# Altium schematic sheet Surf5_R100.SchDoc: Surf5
size A3; DrawnBy: Jaden; Revision: 1.0; SheetNumber: 1; SheetTotal: 1
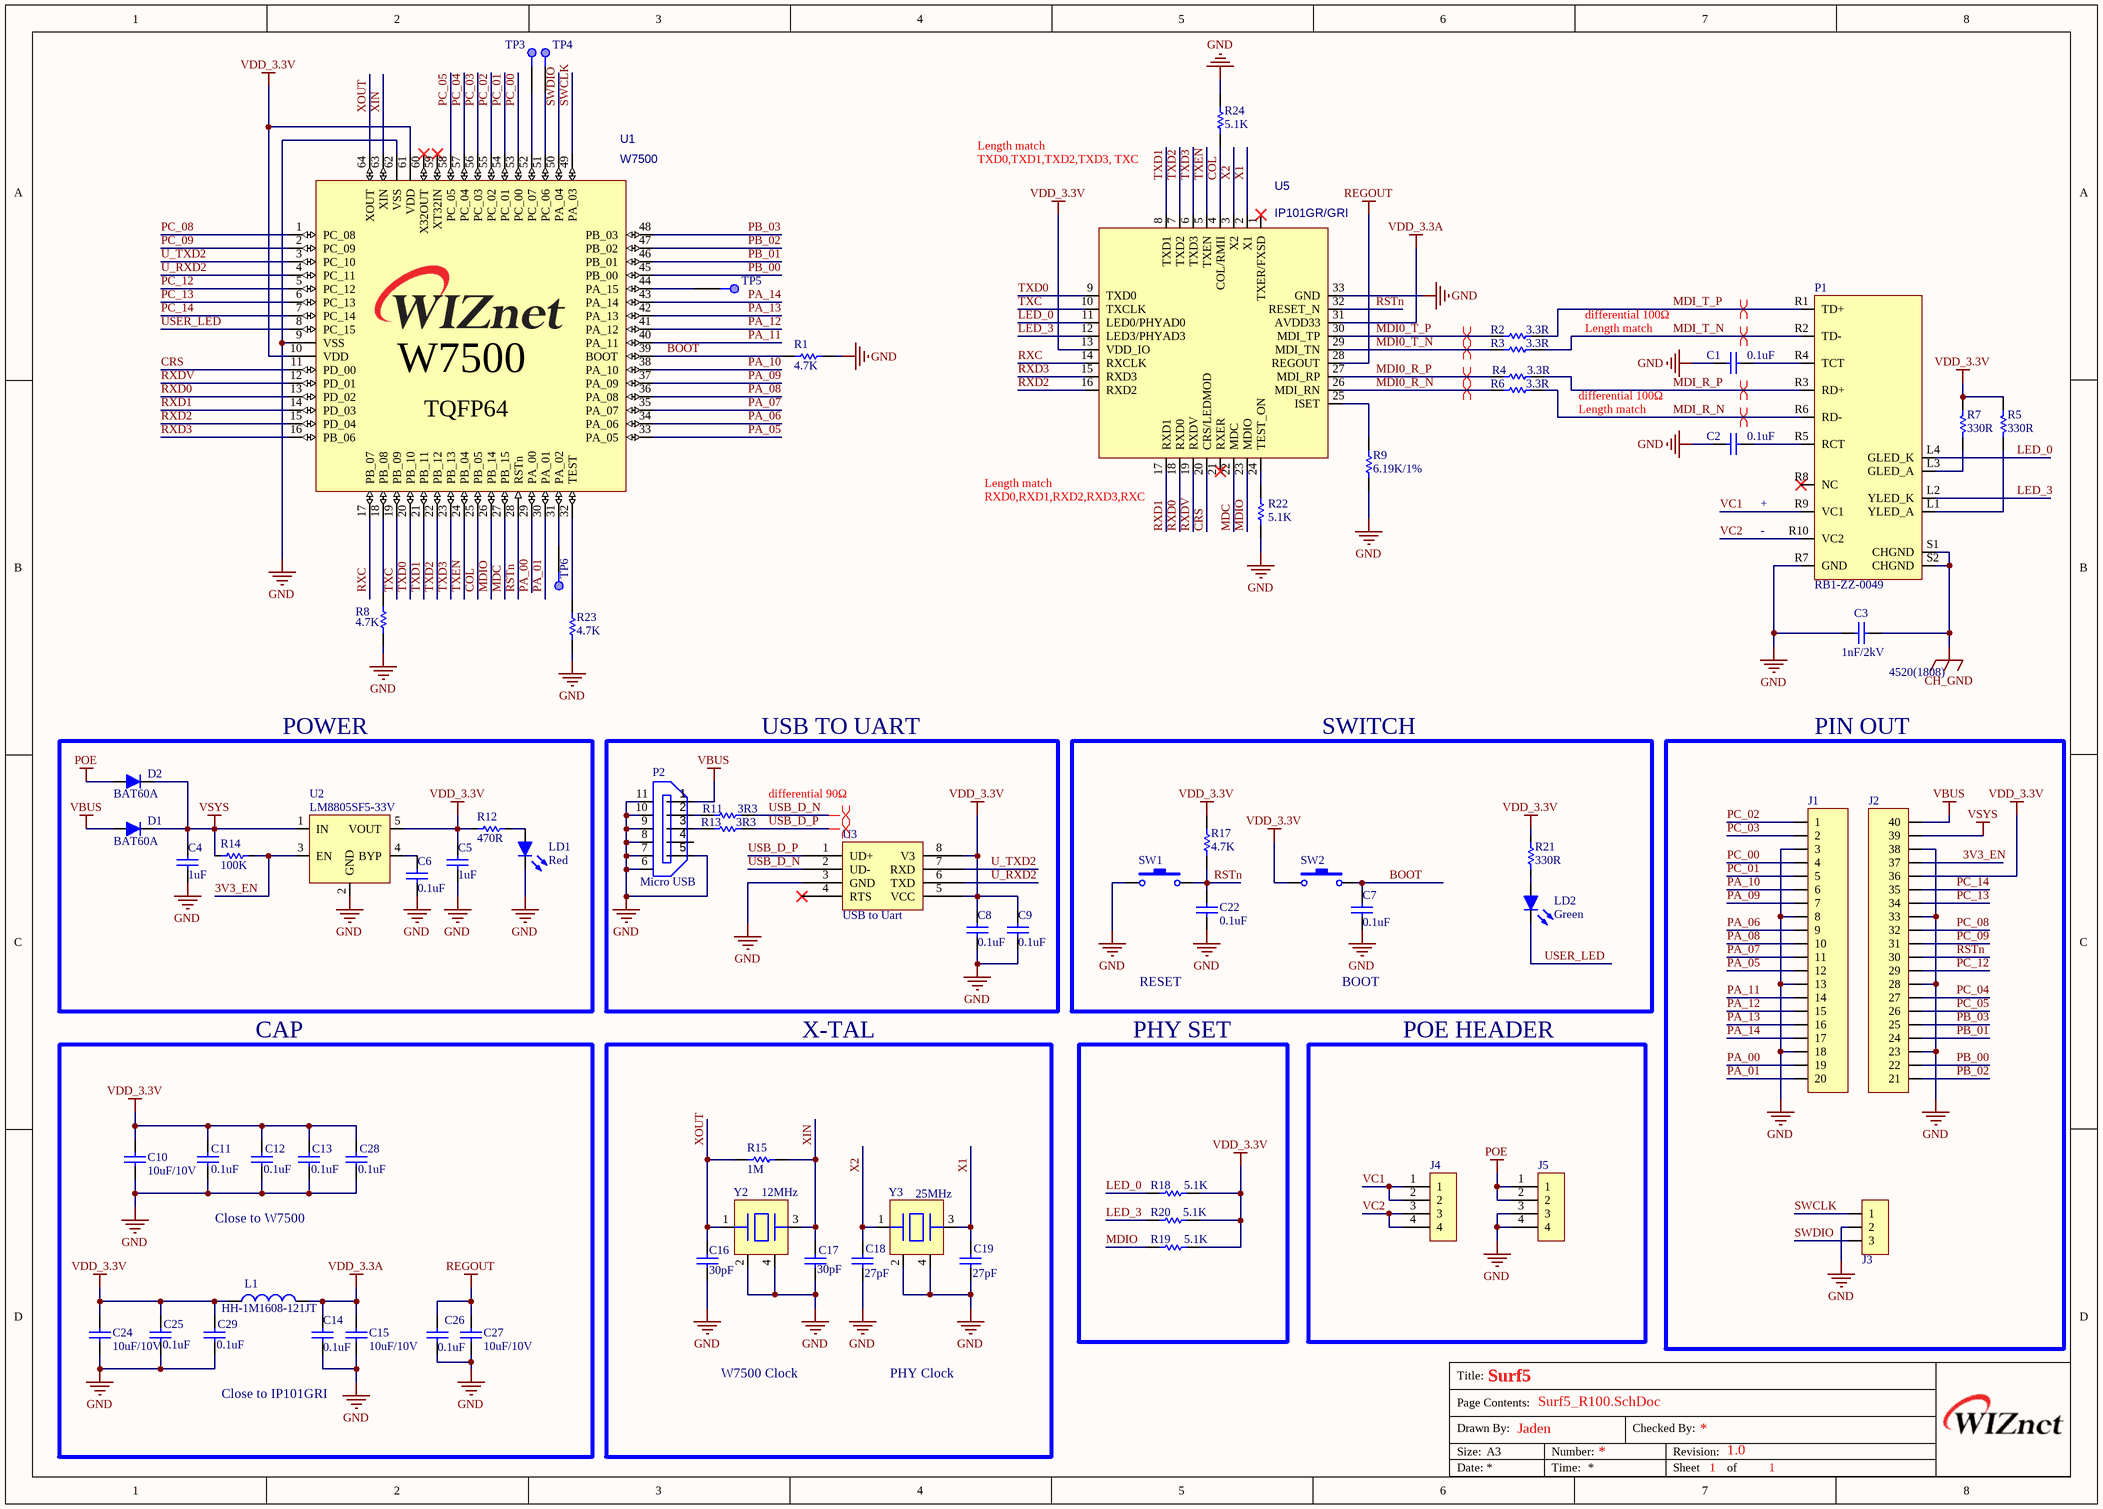
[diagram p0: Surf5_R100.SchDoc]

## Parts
C1  0.1uF  [CAP-0402]
C2  0.1uF  [CAP-0402]
C3  1nF/2kV  [CAP-1808]
C4  1uF  [CAP-0402]
C5  1uF  [CAP-0402]
C6  0.1uF  [CAP-0402]
C7  0.1uF  [CAP-0402]
C8  0.1uF  [CAP-0402]
C9  0.1uF  [CAP-0402]
C10  10uF/10V  [CAP-0805-3]
C11  0.1uF  [CAP-0402]
C12  0.1uF  [CAP-0402]
C13  0.1uF  [CAP-0402]
C14  0.1uF  [CAP-0402]
C15  10uF/10V  [CAP-0805-3]
C16  30pF  [CAP-0402]
C17  30pF  [CAP-0402]
C18  27pF  [CAP-0402]
C19  27pF  [CAP-0402]
C22  0.1uF  [CAP-0402]
C24  10uF/10V  [CAP-0805-3]
C25  0.1uF  [CAP-0402]
C26  0.1uF  [CAP-0402]
C27  10uF/10V  [CAP-0805-3]
C28  0.1uF  [CAP-0402]
C29  0.1uF  [CAP-0402]
D1  BAT60A  [SOD-323(1-C,2-A)]
D2  BAT60A  [SOD-323(1-C,2-A)]
J1  2.54mm 1x20 Pin Header DIP  [IDC-1X20]  (value not drawn)
J2  2.54mm 1x20 Pin Header DIP  [IDC-1X20]  (value not drawn)
J3  2.54mm 1x3 Pin Header DIP  [IDC-1X3]  (value not drawn)
J4  Header Socket 1x4_2.54mm  [Header-Socket(DIP)_4x1_2.54mm]  (value not drawn)
J5  Header Socket 1x4_2.54mm  [Header-Socket(DIP)_4x1_2.54mm]  (value not drawn)
L1  HH-1M1608-121JT  [IND-0603]
LD1  Red  [LED-0603-RED]
LD2  Green  [LED-0603-RED]
P1  RB1-ZZ-0049  [RB1-ZZ-0049]
P2  Micro USB  [Micro 5P B DBX 6.4]
R1  4.7K  [RES-0402]
R2  3.3R  [RES-0402]
R3  3.3R  [RES-0402]
R4  3.3R  [RES-0402]
R5  330R  [RES-0402]
R6  3.3R  [RES-0402]
R7  330R  [RES-0402]
R8  4.7K  [RES-0402]
R9  6.19K/1%  [RES-0402]
R11  3R3  [RES-0402]
R12  470R  [RES-0402]
R13  3R3  [RES-0402]
R14  100K  [RES-0402]
R15  1M  [RES-0402]
R17  4.7K  [RES-0402]
R18  5.1K  [RES-0402]
R19  5.1K  [RES-0402]
R20  5.1K  [RES-0402]
R21  330R  [RES-0402]
R22  5.1K  [RES-0402]
R23  4.7K  [RES-0402]
R24  5.1K  [RES-0402]
SW1  DJT-1115VNS  [1185A]  (value not drawn)
SW2  DJT-1115VNS  [1185A]  (value not drawn)
TP3  TPS  [TPS]  (value not drawn)
TP4  TPS  [TPS]  (value not drawn)
TP5  TPS  [TPS]  (value not drawn)
TP6  TPS  [TPS]  (value not drawn)
U1  W7500  [W7500-LQFP64]
U2  LM8805SF5-33V  [SOT-23-5L]
U3  USB to Uart  [CH340N]
U5  IP101GR/GRI  [QFN32(0.4/4X4)]
Y2  12MHz  [OSC-TZ1067B]
Y3  25MHz  [OSC-82J0626]

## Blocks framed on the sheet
POWER: C4-C6 D1 D2 LD1 R12 R14 U2
USB TO UART: C8 C9 P2 R11 R13 U3
SWITCH: C7 C22 LD2 R17 R21 SW1 SW2
PIN OUT: J1-J3
CAP: C10-C15 C24-C29 L1
X-TAL: C16-C19 R15 Y2 Y3
PHY SET: R18-R20
POE HEADER: J4 J5

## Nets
CH_GND: C3.2 P1.S1(CHGND) P1.S2(CHGND)
GND: C1.1 C2.1 C3.1 C4.1 C5.1 C6.1 C7.1 C8.1 C9.1 C10.1 C11.1 C12.1 C13.1 C14.1 C15.1 C16.1 C17.1 C18.1 C19.1 C22.2 C24.1 C25.1 C26.1 C27.1 C28.1 C29.1 J1.3 J1.8 J1.13 J1.18 J2.3(23) J2.8(28) J2.13(33) J2.18(38) J3.2 J5.3 J5.4 LD1.2(K) P1.R7(GND) P2.5 P2.6 P2.7 P2.8 P2.9 P2.10 P2.11 R1.1 R8.1 R9.1 R22.1 R23.2 R24.2 SW1.1 U1.9(VSS) U1.62(VSS) U2.2(GND) U3.3(GND) U5.33(GND) Y2.2 Y2.4 Y3.2 Y3.4
POE: D2.2(A) J5.1 J5.2
REGOUT: C26.2 C27.2 U5.28(REGOUT)
VBUS: D1.2(A) J2.20(40) P2.1
VDD_3.3A: C14.2 C15.2 L1.2 U5.31(AVDD33)
VDD_3.3V: C5.2 C8.2 C9.2 C10.2 C11.2 C12.2 C13.2 C24.2 C25.2 C28.2 C29.2 J2.16(36) L1.1 R5.1 R7.1 R12.1 R17.1 R18.2 R19.2 R20.2 R21.2 SW2.1 U1.10(VDD) U1.61(VDD) U2.5(VOUT) U3.5(VCC) U3.8(V3) U5.13(VDD_IO)
VSYS: C4.2 D1.1(K) D2.1(K) J2.19(39) R14.1 U2.1(IN)
3V3_EN: J2.17(37) R14.2 U2.3(EN)
BOOT: C7.2 R1.2 SW2.2 U1.39(BOOT)
COL: R24.1 U1.25(PB_05) U5.4(COL/RMII)
CRS: U1.11(PD_00) U5.20(CRS/LEDMOD)
LED_0: P1.L4(GLED_K) R18.1 U5.11(LED0/PHYAD0)
LED_3: P1.L2(YLED_K) R20.1 U5.12(LED3/PHYAD3)
MDC: U1.27(PB_15) U5.22(MDC)
MDI0_R_N: R6.1 U5.26(MDI_RN)
MDI0_R_P: R4.1 U5.27(MDI_RP)
MDI0_T_N: R3.1 U5.29(MDI_TN)
MDI0_T_P: R2.1 U5.30(MDI_TP)
MDI_R_N: P1.R6(RD-) R6.2
MDI_R_P: P1.R3(RD+) R4.2
MDI_T_N: P1.R2(TD-) R3.2
MDI_T_P: P1.R1(TD+) R2.2
MDIO: R19.1 U1.26(PB_14) U5.23(MDIO)
PA_00: J1.19 U1.29(PA_00)
PA_01: J1.20 U1.30(PA_01)
PA_05: J1.12 U1.33(PA_05)
PA_06: J1.9 U1.34(PA_06)
PA_07: J1.11 U1.35(PA_07)
PA_08: J1.10 U1.36(PA_08)
PA_09: J1.7 U1.37(PA_09)
PA_10: J1.6 U1.38(PA_10)
PA_11: J1.14 U1.40(PA_11)
PA_12: J1.15 U1.41(PA_12)
PA_13: J1.16 U1.42(PA_13)
PA_14: J1.17 U1.43(PA_14)
PB_00: J2.2(22) U1.45(PB_00)
PB_01: J2.4(24) U1.46(PB_01)
PB_02: J2.1(21) U1.47(PB_02)
PB_03: J2.5(25) U1.48(PB_03)
PC_00: J1.4 U1.53(PC_00)
PC_01: J1.5 U1.54(PC_01)
PC_02: J1.1 U1.55(PC_02)
PC_03: J1.2 U1.56(PC_03)
PC_04: J2.7(27) U1.57(PC_04)
PC_05: J2.6(26) U1.58(PC_05)
PC_08: J2.12(32) U1.1(PC_08)
PC_09: J2.11(31) U1.2(PC_09)
PC_12: J2.9(29) U1.5(PC_12)
PC_13: J2.14(34) U1.6(PC_13)
PC_14: J2.15(35) U1.7(PC_14)
RSTn: C22.1 J2.10(30) R17.2 SW1.2 U1.28(RSTn) U5.32(RESET_N)
RXC: U1.17(PB_07) U5.14(RXCLK)
RXD0: U1.13(PD_02) U5.18(RXD0)
RXD1: U1.14(PD_03) U5.17(RXD1)
RXD2: U1.15(PD_04) U5.16(RXD2)
RXD3: U1.16(PB_06) U5.15(RXD3)
RXDV: U1.12(PD_01) U5.19(RXDV)
SWCLK: J3.1 U1.49(PA_03)
SWDIO: J3.3 U1.50(PA_04)
TXC: U1.19(PB_09) U5.10(TXCLK)
TXD0: U1.20(PB_10) U5.9(TXD0)
TXD1: U1.21(PB_11) U5.8(TXD1)
TXD2: U1.22(PB_12) U5.7(TXD2)
TXD3: U1.23(PB_13) U5.6(TXD3)
TXEN: U1.24(PB_04) U5.5(TXEN)
U_RXD2: U1.4(PC_11) U3.6(TXD)
U_TXD2: U1.3(PC_10) U3.7(RXD)
USB_D_N: R11.2 U3.2(UD-)
USB_D_P: R13.2 U3.1(UD+)
USER_LED: LD2.2(K) U1.8(PC_15)
VC1: J4.1 J4.2 P1.R9(VC1)
VC2: J4.3 J4.4 P1.R10(VC2)
X1: C19.2 U5.2(X1) Y3.3
X2: C18.2 U5.3(X2) Y3.1
XIN: C17.2 R15.2 U1.63(XIN) Y2.3
XOUT: C16.2 R15.1 U1.64(XOUT) Y2.1
NetC1_2: C1.2 P1.R4(TCT)
NetC2_2: C2.2 P1.R5(RCT)
NetC6_2: C6.2 U2.4(BYP)
NetLD1_1: LD1.1(A) R12.2
NetLD2_1: LD2.1(A) R21.1
NetP1_L1: P1.L1(YLED_A) R5.2
NetP1_L3: P1.L3(GLED_A) R7.2
NetP2_2: P2.2 R11.1
NetP2_3: P2.3 R13.1
NetR8_2: R8.2 U1.18(PB_08)
NetR9_2: R9.2 U5.25(ISET)
NetR22_2: R22.2 U5.24(TEST_ON)
NetR23_1: R23.1 U1.32(TEST)
NetTP3_1: TP3.1 U1.52(PC_07)
NetTP4_1: TP4.1 U1.51(PC_06)
NetTP5_1: TP5.1 U1.44(PA_15)
NetTP6_1: TP6.1 U1.31(PA_02)

Not connected (* = marked no-connect by the designer): P1 R8(NC)*; P2 4; U1 59(XT32IN)* 60(X32OUT)*; U3 4(RTS)*; U5 1(TXER/FXSD)* 21(RXER)*

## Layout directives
differential pair: MDI0_R_N, MDI0_R_P, MDI0_T_N, MDI0_T_P, MDI_R_N, MDI_R_P, MDI_T_N, MDI_T_P, USB_D_N, USB_D_P

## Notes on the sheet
- Length match
- TXD0,TXD1,TXD2,TXD3, TXC
- differential 100Ω
- (near U5) Length match
- (near U5) RXD0,RXD1,RXD2,RXD3,RXC
- +
- (near P1) -
- (near C3) 4520(1808)
- differential 90Ω
- RESET
- BOOT
- Close to W7500
- Close to IP101GRI
- W7500 Clock
- PHY Clock

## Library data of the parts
C1 C2 C4-C9 C11-C14 C16-C19 C22 C25 C26 C28 C29 = CAP-0402: Ceramic CAP 0402(1005)
C3 = CAP-1808: Ceramic CAP 1808(4520)
C10 C15 C24 C27 = CAP-0805: MLCC-0805(2012)
D1 D2 = DIODE-BAT60A: Silicon Schottky Diode
J4 J5 = Header Socket 1x4_2.54mm: Connector; Manufacturer_Name: Harwin; Manufacturer_Part_Number: M20-7820442
L1 = IND-0603: Inductor 0603(1608)
LD1 LD2 = LED-0603
P1 = RB1-ZZ-0049: PoE RJ45
P2 = Micro USB 5P DBX6.4: Micro USB B Connector SMD
R1-R9 R11-R15 R17-R24 = RES-0402
SW1 SW2 = ITS-1107(SMD): TACT Switch (SMD)
TP3-TP6 = TPS: Test_point; Manufacturer: Wurth Elektronik; Part Number: 61300211121; Rated Current: 3A; Gender: Male; Withstanding Voltage: 500VAC; Working Voltage: 250VAC; Pitch: 2.54mm; Contact Resistance: 20mOhm; Row Number: Single; Pin Number: 2
U1 = W7500: WIZnet ARM Cortex-M0
U2 = LM8805SF5-33V: 600mA CMOS LDO Regulator
U3 = CH340N
U5 = IP101GR/GRI: Pakage: VQFN-32
Y2 = OSC-TZ1067B-12MHz: X-tal 12MHz,3.2x2.5 SMD, CL=20pF
Y3 = OSC-82J0626-25MHz: X-tal 25MHz,3.2x2.5 SMD, CL=18pF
